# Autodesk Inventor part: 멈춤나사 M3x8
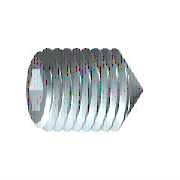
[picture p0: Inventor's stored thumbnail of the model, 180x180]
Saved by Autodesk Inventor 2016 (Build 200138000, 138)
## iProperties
Created: 2012-02
Part Number: 멈춤나사 M3x8
Material: 강철, 연강
Description: 6각 소켓 머리 없는 멈춤 나사
Document SubType Name: Modeling
Standard: KS B 1028
Designer: mduedu
Standards Organization: KS
Language: ko-KR
Size Designation: 원추점 M3x8
Categories: <MemberInstance><Categories><Category DisplayName="조임쇠" InternalName="e4da775c-781d-43d5-af7c-5136215cf5a6" Mnemonic="FSTN"><Category DisplayName="볼트" InternalN
Density: 7.86 g/cm^3
Mass: 0.360339 g
Surface Area: 0.888172 cm^2
Volume: 0.0458447 cm^3
Appearance: 강철
IsCustomPart: 1
Author: mduedu
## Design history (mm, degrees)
sketch "스케치1"
  geometry: L1 (0, 0)-(5.5, 0); L2 (8, 0.866)-(8, 1.5); L3 (8, 1.5)-(0, 1.5); L4 (8, 0.866)-(6, 0.866); L5 (6, 0.866)-(5.5, 0); L6 (0, -0.3)-(0, 1.8) reference; L7 (0, 1.5)-(0, 0)
  constraints: 13 end point, 3 parallel, 1 collinear, 1 perpendicular, 1 point on line
  dimensions: "d0" = 2 distance of L2.start L4.end (= INTI); "d1" = 60 deg angle of L5 L1; "d2" = 3 diameter of L3 L1 (= NND); "d3" = 1.73205 diameter of L4 L1 (= 1.1547 x SW); "d5" = 8 distance from line of L2 L3.end (= NLG)
revolve "본체" sketch "스케치1" stored, may be unused: angle "d6" = 90 deg
sketch "스케치2"
  geometry: L1 (-0.433, 0.75)-(0.433, 0.75); L2 (0.433, 0.75)-(0.866, 0); L3 (0.866, 0)-(0.433, -0.75); L4 (0.433, -0.75)-(-0.433, -0.75); L5 (-0.433, -0.75)-(-0.866, 0); L6 (-0.866, 0)-(-0.433, 0.75); 3 further points
  constraints: 12 end point, 1 coincident, 1 horizontal, 13 other
extrude "슬롯" join sketch "스케치2" taper "d7" = 0 deg; stored distance "d21" = 10
workaxis "Work Axis1"
workplane "Work Plane1"
sketch "스케치5"
  geometry: L1 (-4, -0.15)-(-2.65, -1.5) reference; L2 (-4, 0.15)-(-2.65, 1.5) reference; L3 (-2.65, 1.5)-(-4.15, 0); L4 (-2.65, -1.5)-(-4.15, 0); 1 further point
  constraints: 4 end point, 1 horizontal alignment, 1 perpendicular
node "작업점1"
body "Solid1"
feature "스레드" dims "d12" = 8 (= NLG), "d13" = 0
chamfer "모따기1" distance "d8" = 1.35 (computed from NND, SPD, FAWI); stored, may be unused: angle "d9" = 45 deg (= FAWI), second distance "d34" = 1.35 (computed from NND, SPD, FAWI)
chamfer "모따기2" distance "d10" = 0.30673 (= -0.5 x GD1 + 0.5 x NND); stored, may be unused: angle "d11" = 45 deg (= FAWI), second distance "d35" = 0.30673 (= -0.5 x GD1 + 0.5 x NND)
other parameters: "NND" = 3 [user parameter; used in 5 equation terms], "NLG" = 8 [user parameter; used in 2 equation terms], "INTI" = 2 [user parameter; used in 1 equation term], "FAWI" = 45 deg [user parameter; used in 4 equation terms], "SW" = 1.5 [user parameter; used in 2 equation terms], "GD1" = 2.38655 (= THREADDIA - 1.2269 x PTC) [user parameter; used in 2 equation terms], "d4" = 0, "FAWI1" = 45 deg [user parameter], "SPD" = 0.3 [user parameter; used in 2 equation terms], "d36" = 0, "d37" = 0, "GUL" = 0.30673 (= 0.61345 x PTC) [user parameter], "TOA" = 30 deg [user parameter], "THREADDIA" = 3 [user parameter; used in 1 equation term], "PTC" = 0.5 [user parameter; used in 4 equation terms], "GAL" = 0.30673 (= 0.61345 x PTC) [user parameter], "E0" = 1.7325 (= 1.155 x SW) [user parameter]
